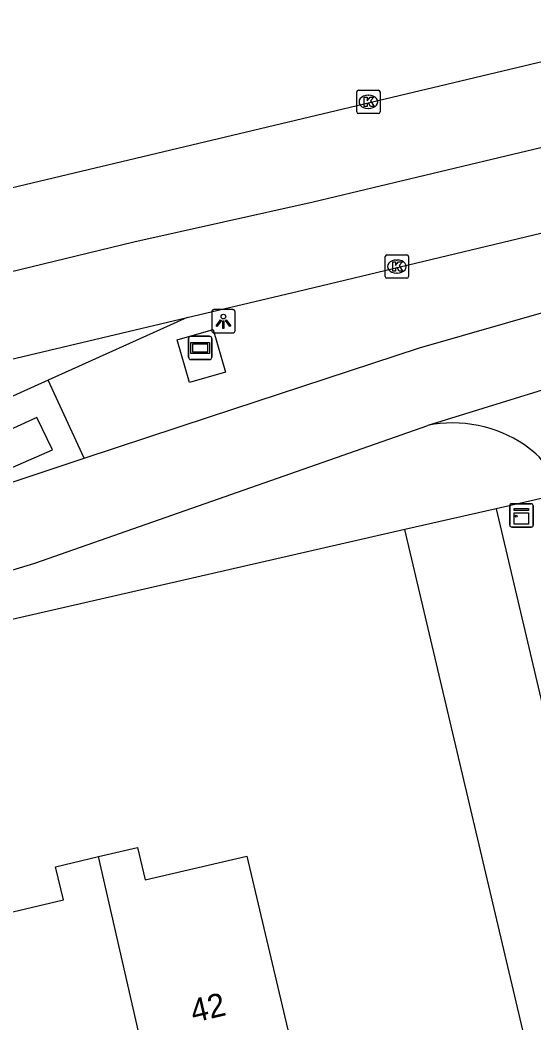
# Model space of a CAD drawing. Extents: x 158038 to 159242, y 380133 to 381214.
# Drawn here: x 158628.91 to 158650.9, y 380973.99 to 381016.88 of the extents above; entities that cross this region are included whole.
import ezdxf

# ---------------------------------------------------------------- set-up
doc = ezdxf.new("R2010")
doc.units = 0
for name, color, linetype in [('IMGEO_Fietspad_open', 7, 'Continuous'), ('IMGEO_Groenvoorziening', 7, 'Continuous'), ('IMGEO_Kast', 7, 'Continuous'), ('IMGEO_Kolk', 7, 'Continuous'), ('IMGEO_Lichtpunt', 7, 'Continuous'), ('IMGEO_OVBaan_gesloten', 7, 'Continuous'), ('IMGEO_Pand', 7, 'Continuous'), ('IMGEO_Pand_nummerreeks', 7, 'Continuous'), ('IMGEO_Reclamebord', 7, 'Continuous'), ('IMGEO_Rijbaan_regionaal_gesloten', 7, 'Continuous'), ('IMGEO_Voetpad_gesloten', 7, 'Continuous'), ('IMGEO_Voetpad_open', 7, 'Continuous')]:
    doc.layers.add(name, color=color, linetype=linetype)

msp = doc.modelspace()

# ---------------------------------------------------------------- linework, layer by layer
at = {"layer": 'IMGEO_Fietspad_open'}
for points in [[(158631.65, 380998.147), (158637.012, 380999.915), (158646, 381002.859), (158655.094, 381005.47), (158664.276, 381007.743), (158666.916, 381008.345)], [(158651.852, 381001.234), (158646.352, 380999.546)], [(158543.487, 380975.057), (158559.5, 380977.024), (158569.881, 380979.588), (158585.768, 380983.41), (158590.087, 380984.449), (158613.803, 380989.844), (158626.388, 380992.815), (158628.561, 380993.352), (158629.543, 380993.657), (158646.352, 380999.546)], [(158542.093, 380977.956), (158559.031, 380980.009), (158584.646, 380986.212), (158588.305, 380987.098), (158625.313, 380996.031), (158631.65, 380998.147)]]:
    msp.add_lwpolyline(points, dxfattribs=at)
for centre, radius, start, end in [((158647.42, 380994.164), 5.487, 56.0012, 101.2245), ((158648.452, 380995.612), 3.709, 16.6491, 56.7119)]:
    msp.add_arc(centre, radius, start, end, dxfattribs=at)
at = {"layer": 'IMGEO_Groenvoorziening'}
for points in [[(158649.276, 380995.98), (158661.198, 380945.385)], [(158657.305, 380944.468), (158645.377, 380995.088)]]:
    msp.add_lwpolyline(points, dxfattribs=at)
at = {"layer": 'IMGEO_Kast'}
for p, q in [((158649.937, 380996.199), (158650.778, 380996.199)), ((158650.778, 380996.199), (158649.937, 380996.199)), ((158649.862, 380995.274), (158649.862, 380996.115)), ((158649.862, 380996.115), (158649.862, 380995.274)), ((158650.862, 380996.124), (158650.862, 380995.283)), ((158650.862, 380995.283), (158650.862, 380996.124)), ((158650.787, 380995.199), (158649.946, 380995.199)), ((158649.946, 380995.199), (158650.787, 380995.199))]:
    msp.add_line(p, q, dxfattribs=at)
for points in [[(158650.057, 380995.989), (158650.657, 380995.989), (158650.657, 380995.904), (158650.057, 380995.904), (158650.057, 380995.989)], [(158650.057, 380995.814), (158650.657, 380995.814), (158650.657, 380995.325), (158650.057, 380995.325), (158650.057, 380995.814)]]:
    msp.add_lwpolyline(points, dxfattribs=at)
msp.add_circle((158650.141, 380995.663), 0.0377, dxfattribs=at)
for centre, start, end in [((158649.94, 380996.121), 92.4484, 184.2845), ((158649.94, 380996.121), 92.4484, 184.2845), ((158650.784, 380996.121), 2.4484, 94.2845), ((158650.784, 380996.121), 2.4484, 94.2845), ((158649.94, 380995.277), 182.4484, 274.2845), ((158649.94, 380995.277), 182.4484, 274.2845), ((158650.784, 380995.277), 272.4484, 4.2845), ((158650.784, 380995.277), 272.4484, 4.2845)]:
    msp.add_arc(centre, 0.0779, start, end, dxfattribs=at)
at = {"layer": 'IMGEO_Kolk'}
for p, q in [((158643.313, 381012.959), (158643.313, 381013.811)), ((158643.388, 381013.885), (158644.24, 381013.885)), ((158644.314, 381013.811), (158644.314, 381012.959)), ((158643.801, 381013.665), (158643.826, 381013.665)), ((158643.824, 381013.105), (158643.799, 381013.105)), ((158644.24, 381012.885), (158643.388, 381012.885)), ((158644.532, 381005.914), (158644.532, 381006.766)), ((158644.607, 381006.84), (158645.459, 381006.84)), ((158645.02, 381006.62), (158645.045, 381006.62)), ((158645.533, 381006.766), (158645.533, 381005.914)), ((158645.043, 381006.06), (158645.018, 381006.06)), ((158645.459, 381005.84), (158644.607, 381005.84))]:
    msp.add_line(p, q, dxfattribs=at)
for points in [[(158643.313, 381012.959), (158643.313, 381013.811)], [(158643.388, 381013.885), (158644.24, 381013.885)], [(158644.314, 381013.811), (158644.314, 381012.959)], [(158643.634, 381013.585), (158643.757, 381013.585), (158643.757, 381013.434), (158643.887, 381013.585), (158644.051, 381013.585), (158643.905, 381013.434), (158644.058, 381013.185), (158643.906, 381013.185), (158643.821, 381013.349), (158643.757, 381013.282), (158643.757, 381013.185), (158643.634, 381013.185), (158643.634, 381013.585)], [(158644.24, 381012.885), (158643.388, 381012.885)], [(158644.532, 381005.914), (158644.532, 381006.766)], [(158644.607, 381006.84), (158645.459, 381006.84)], [(158644.853, 381006.54), (158644.976, 381006.54), (158644.976, 381006.389), (158645.106, 381006.54), (158645.27, 381006.54), (158645.124, 381006.389), (158645.277, 381006.14), (158645.125, 381006.14), (158645.04, 381006.304), (158644.976, 381006.237), (158644.976, 381006.14), (158644.853, 381006.14), (158644.853, 381006.54)], [(158645.533, 381006.766), (158645.533, 381005.914)], [(158645.459, 381005.84), (158644.607, 381005.84)]]:
    msp.add_lwpolyline(points, dxfattribs=at)
for centre, start, end in [((158643.39, 381013.809), 91.552, 178.448), ((158643.39, 381013.809), 91.552, 178.448), ((158644.238, 381013.809), 1.552, 88.448), ((158644.238, 381013.809), 1.552, 88.448), ((158643.39, 381012.961), 181.552, 268.448), ((158643.39, 381012.961), 181.552, 268.448), ((158644.238, 381012.961), 271.552, 358.448), ((158644.238, 381012.961), 271.552, 358.448), ((158644.609, 381006.764), 91.552, 178.448), ((158644.609, 381006.764), 91.552, 178.448), ((158645.457, 381006.764), 1.552, 88.448), ((158645.457, 381006.764), 1.552, 88.448), ((158644.609, 381005.916), 181.552, 268.448), ((158644.609, 381005.916), 181.552, 268.448), ((158645.457, 381005.916), 271.552, 358.448), ((158645.457, 381005.916), 271.552, 358.448)]:
    msp.add_arc(centre, 0.0765, start, end, dxfattribs=at)
for centre, major_axis, ratio, start_param, end_param in [((158643.8, 381013.385), (-0.387, 0.002), 0.722429, 4.712389, 7.853982), ((158643.825, 381013.385), (-0.39, 0.002), 0.717154, 1.570796, 4.712389), ((158645.019, 381006.34), (-0.387, 0.002), 0.722429, 4.712389, 7.853982), ((158645.044, 381006.34), (-0.39, 0.002), 0.717154, 1.570796, 4.712389)]:
    msp.add_ellipse(centre, major_axis=major_axis, ratio=ratio, start_param=start_param, end_param=end_param, dxfattribs=at)
at = {"layer": 'IMGEO_Lichtpunt'}
for p, q in [((158637.113, 381004.402), (158637.113, 381003.595)), ((158637.113, 381004.402), (158637.113, 381003.595)), ((158638.015, 381004.497), (158637.207, 381004.497)), ((158638.015, 381004.497), (158637.207, 381004.497)), ((158638.109, 381003.595), (158638.109, 381004.402)), ((158638.109, 381003.595), (158638.109, 381004.402)), ((158637.207, 381003.501), (158638.015, 381003.501)), ((158637.207, 381003.501), (158638.015, 381003.501))]:
    msp.add_line(p, q, dxfattribs=at)
for points in [[(158637.487, 381004.066), (158637.526, 381004.038), (158637.338, 381003.776), (158637.3, 381003.803), (158637.487, 381004.066)], [(158637.589, 381004.018), (158637.636, 381004.018), (158637.636, 381003.696), (158637.589, 381003.696), (158637.589, 381004.018)], [(158637.699, 381004.038), (158637.737, 381004.065), (158637.924, 381003.803), (158637.885, 381003.775), (158637.699, 381004.038)]]:
    msp.add_lwpolyline(points, dxfattribs=at)
msp.add_circle((158637.612, 381004.2), 0.0994, dxfattribs=at)
for centre, start, end in [((158637.207, 381004.402), 90, 180), ((158637.207, 381004.402), 90, 180), ((158638.015, 381004.402), 0, 90), ((158638.015, 381004.402), 0, 90), ((158637.207, 381003.595), 180, 270), ((158637.207, 381003.595), 180, 270), ((158638.015, 381003.595), 270, 0), ((158638.015, 381003.595), 270, 360)]:
    msp.add_arc(centre, 0.0946, start, end, dxfattribs=at)
at = {"layer": 'IMGEO_OVBaan_gesloten'}
for points in [[(158589.186, 380993.035), (158636.057, 381004.158)], [(158636.057, 381004.158), (158630.122, 381001.484)], [(158630.122, 381001.484), (158624.404, 380998.908), (158622.946, 380998.253), (158603.198, 380993.535), (158589.186, 380993.035)]]:
    msp.add_lwpolyline(points, dxfattribs=at)
at = {"layer": 'IMGEO_Pand'}
for points in [[(158632.27, 380981.102), (158633.941, 380981.495), (158634.268, 380980.105), (158638.618, 380981.129), (158640.668, 380972.423), (158637.072, 380971.576), (158638.257, 380966.543), (158635.728, 380965.948)], [(158626.719, 380978.3), (158630.769, 380979.253), (158630.435, 380980.67), (158632.27, 380981.102)], [(158635.728, 380965.948), (158632.27, 380981.102)]]:
    msp.add_lwpolyline(points, dxfattribs=at)
at = {"layer": 'IMGEO_Reclamebord'}
for p, q in [((158636.122, 381002.461), (158636.122, 381003.261)), ((158636.122, 381003.261), (158636.122, 381002.461)), ((158636.222, 381003.361), (158637.012, 381003.361)), ((158637.012, 381003.361), (158636.222, 381003.361)), ((158637.112, 381003.261), (158637.112, 381002.461)), ((158637.112, 381002.461), (158637.112, 381003.261)), ((158637.012, 381002.361), (158636.222, 381002.361)), ((158636.222, 381002.361), (158637.012, 381002.361))]:
    msp.add_line(p, q, dxfattribs=at)
for points in [[(158636.223, 381003.093), (158637.011, 381003.093), (158637.011, 381002.629), (158636.223, 381002.629), (158636.223, 381003.093)], [(158636.288, 381003.028), (158636.288, 381002.694), (158636.946, 381002.694), (158636.946, 381003.028), (158636.288, 381003.028)]]:
    msp.add_lwpolyline(points, dxfattribs=at)
for centre, start, end in [((158636.222, 381003.261), 90, 180), ((158636.222, 381003.261), 90, 180), ((158637.012, 381003.261), 0, 90), ((158637.012, 381003.261), 360, 90), ((158636.222, 381002.461), 180, 270), ((158636.222, 381002.461), 180, 270), ((158637.012, 381002.461), 270, 0), ((158637.012, 381002.461), 270, 0)]:
    msp.add_arc(centre, 0.1, start, end, dxfattribs=at)
at = {"layer": 'IMGEO_Rijbaan_regionaal_gesloten'}
for points in [[(158576.573, 380997.347), (158579.871, 380998.132), (158587.716, 381000), (158662.869, 381017.892)], [(158666.627, 381015.107), (158656.933, 381012.791), (158649.096, 381010.919), (158641.451, 381009.092), (158633.779, 381007.383), (158626.007, 381005.501), (158610.716, 381001.898), (158603.036, 381000.089), (158594.635, 380998.11), (158587.508, 380996.381), (158583.848, 380995.494), (158581.18, 380994.864), (158575.946, 380993.627), (158568.275, 380991.816), (158560.604, 380990.004)], [(158636.057, 381004.158), (158640.823, 381005.286), (158655.245, 381008.744), (158666.288, 381011.416)]]:
    msp.add_lwpolyline(points, dxfattribs=at)
at = {"layer": 'IMGEO_Voetpad_gesloten'}
msp.add_lwpolyline([(158626.906, 380998.65), (158627.576, 380997.313), (158630.299, 380998.504), (158629.637, 380999.888), (158626.906, 380998.65)], dxfattribs=at)
at = {"layer": 'IMGEO_Voetpad_open'}
for points in [[(158637.697, 381001.819), (158636.158, 381001.379), (158635.639, 381003.207), (158637.177, 381003.646), (158637.697, 381001.819)], [(158631.65, 380998.147), (158630.122, 381001.484)], [(158651.455, 380996.478), (158649.276, 380995.98)], [(158649.276, 380995.98), (158645.377, 380995.088)], [(158645.377, 380995.088), (158628.269, 380991.174), (158587.594, 380981.5), (158587.388, 380981.452)]]:
    msp.add_lwpolyline(points, dxfattribs=at)

# ---------------------------------------------------------------- texts
at = {"layer": 'IMGEO_Pand_nummerreeks'}
msp.add_text('42', height=1, rotation=13.2405, dxfattribs=at).set_placement((158636.334, 380973.992))

doc.saveas('drawing.dxf')
